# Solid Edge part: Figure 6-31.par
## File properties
Author: TIET
Template: Iso Metric Part.par
Last saved by: CADCIM
Revision: 3
Application: Solid Edge
Accuracy: 0.990
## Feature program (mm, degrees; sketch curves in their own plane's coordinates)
base feature "unnamed BaseFeature 1"
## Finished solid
Body 1: solid body, 9 faces, 21 edges, 14 vertices.
  Faces by surface: plane 8, spline 1
  Edges by curve: line 17, intersection 2, spline 2
Bounding box of the edges (mm; curved faces can reach further): 98.047 x 93.394 x 56.044, from (-49.0237, 0, 0) to (49.0237, 93.3941, 56.0443).
Planar faces by outward normal: +x 1, +y 1, +z 2, -x 1, -y 2, -z 1
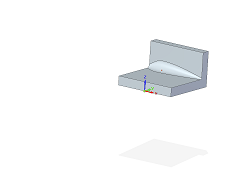
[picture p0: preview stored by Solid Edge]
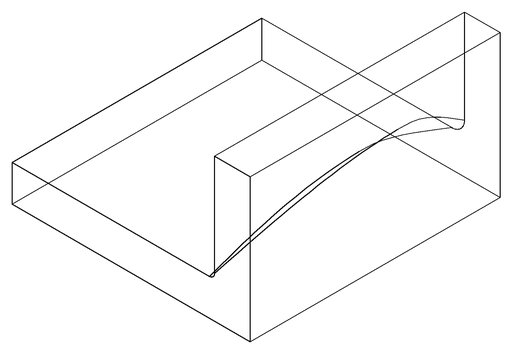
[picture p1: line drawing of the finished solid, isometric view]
